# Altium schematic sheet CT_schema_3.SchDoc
size 421 x 351 mm
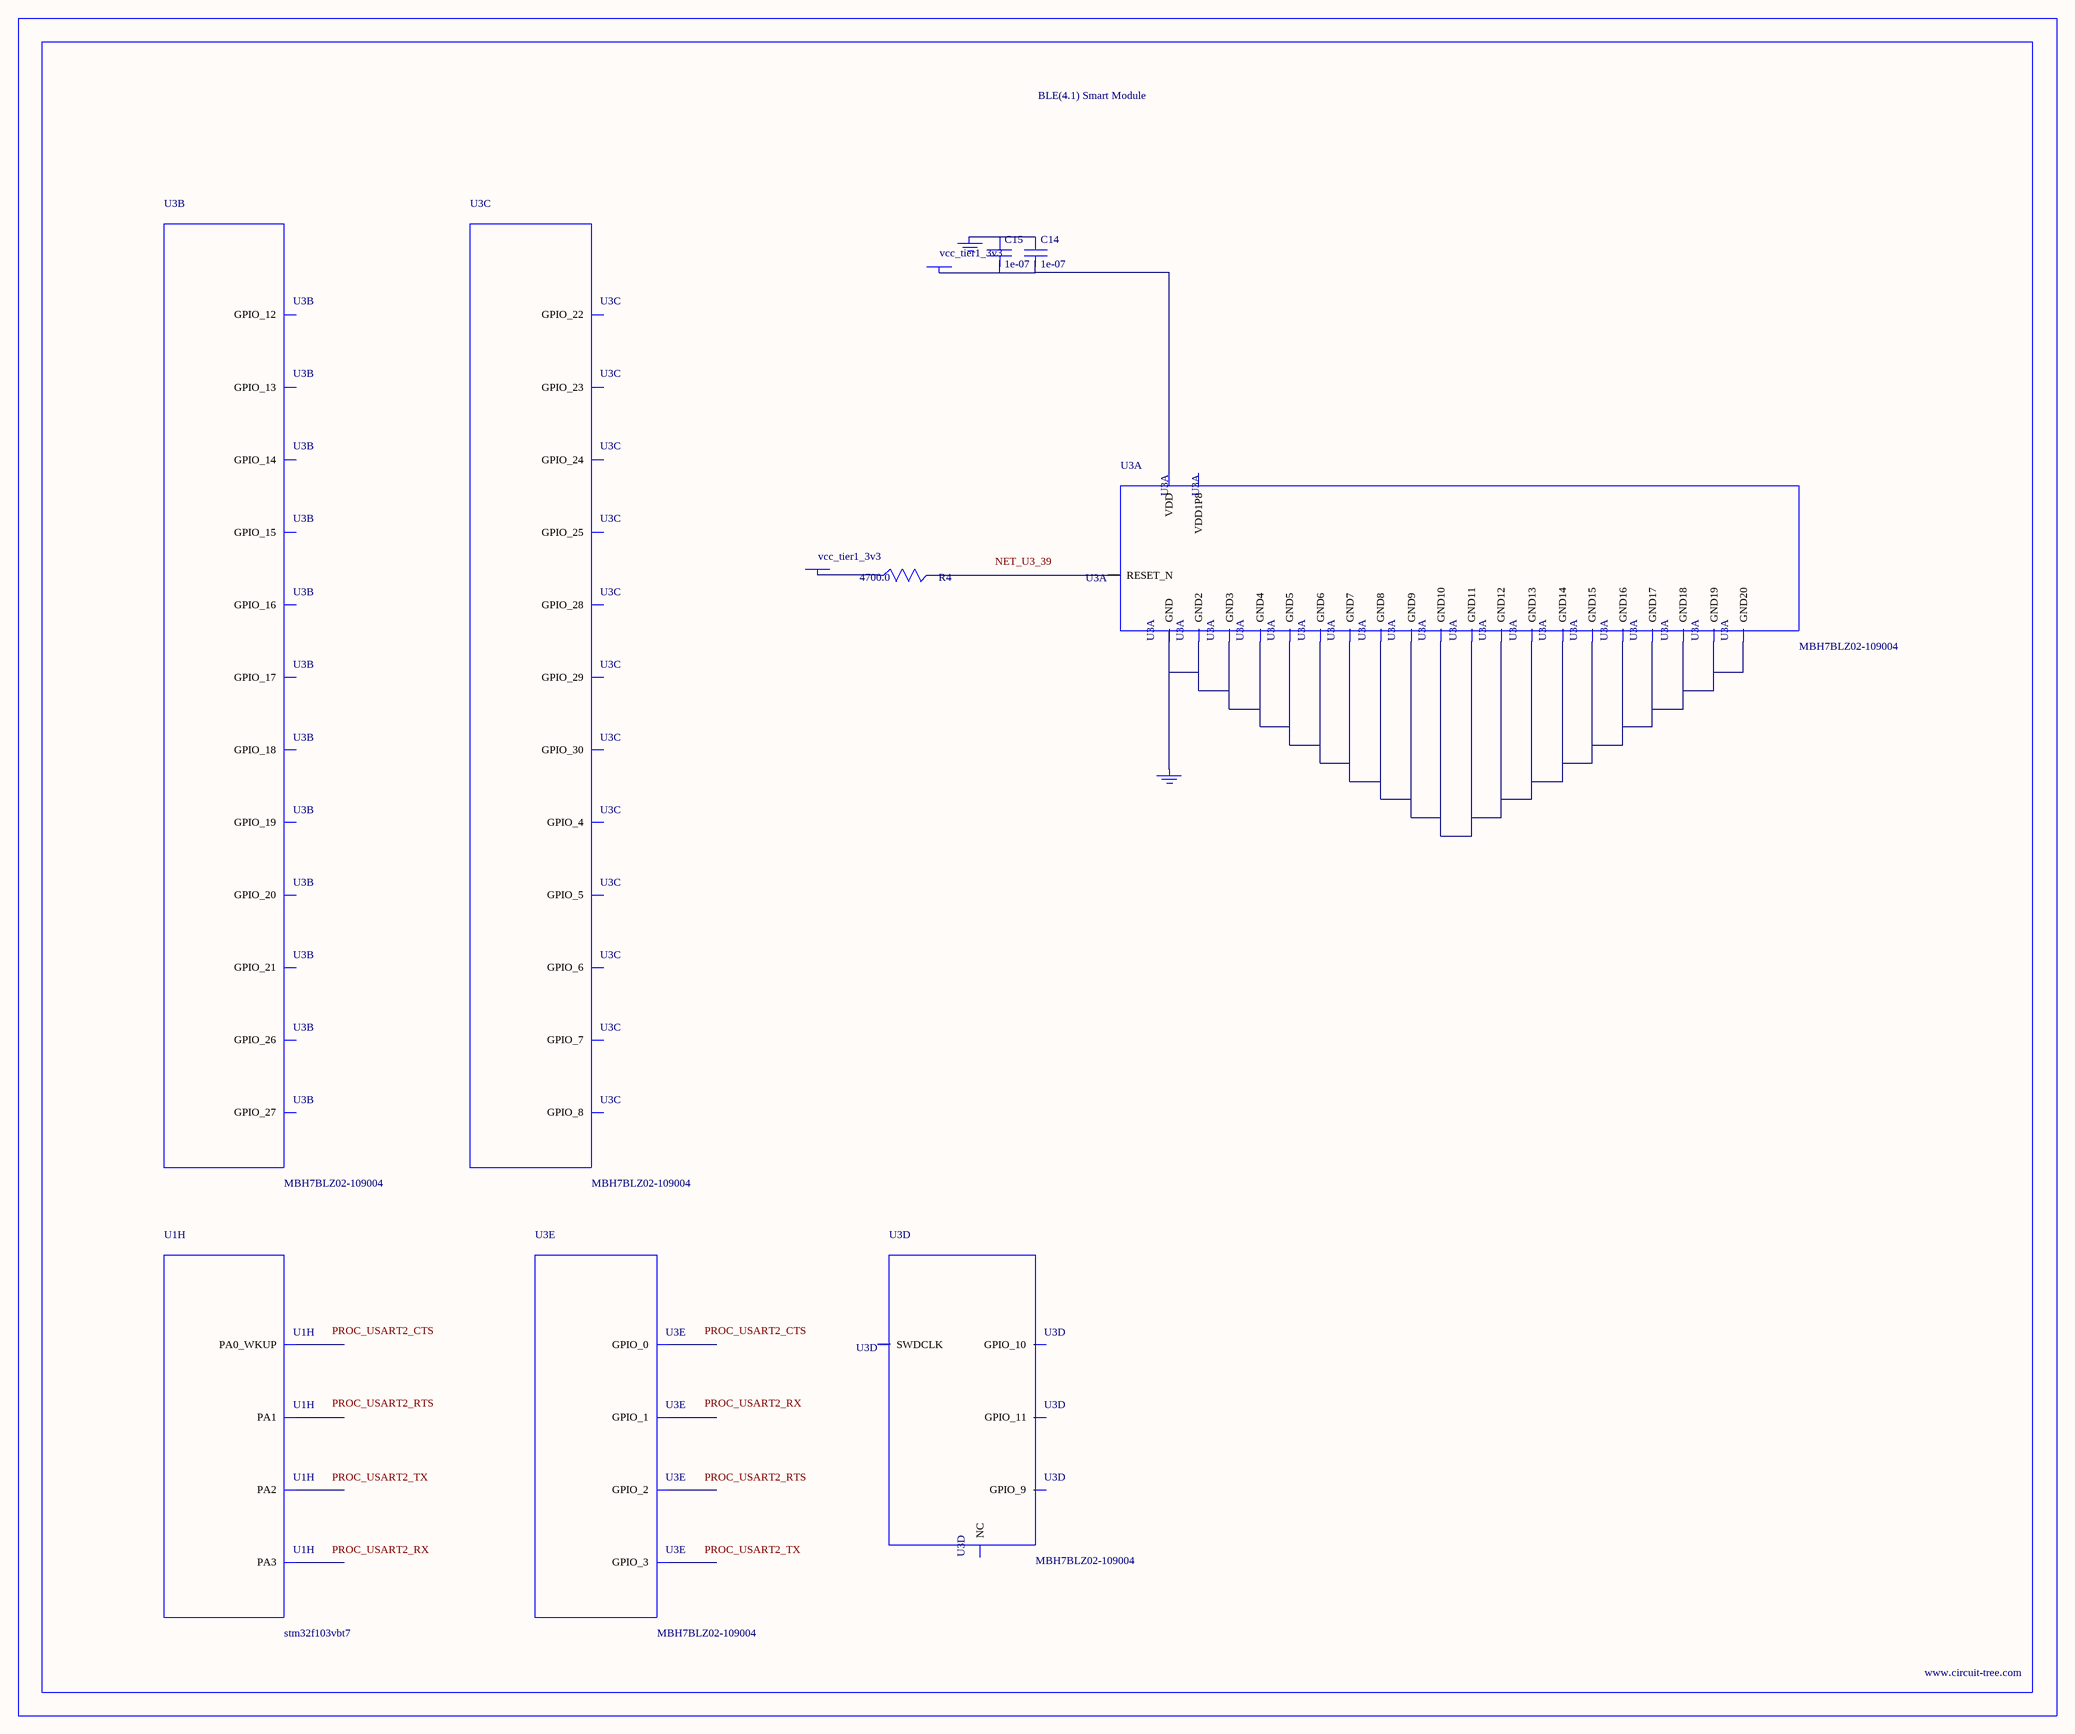
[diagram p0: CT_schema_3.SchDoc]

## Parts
BORDER2  (no value)
C14  1e-07  [C0402]
C15  1e-07  [C0402]
GND_INSTANCE_2_0  (no value)
GND_INSTANCE_2_1  (no value)
POWER_INSTANCE_2_0  vcc_tier1_3v3
POWER_INSTANCE_2_1  vcc_tier1_3v3
R4  4700.0  [R0603]
U1  stm32f103vbt7  [LQFP100]  (part H of 11)
U3  MBH7BLZ02-109004  [MBH7BLZ02-109004]  (parts A,B,C,D,E of 5)

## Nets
NetC14_1: C14.1 C15.1 GND_INSTANCE_2_0.0(GND)
NetC14_2: C14.2 C15.2 POWER_INSTANCE_2_0.0(PWR) U3.28(VDD)
NetGND_INSTANCE_2_1_0: GND_INSTANCE_2_1.0(GND) U3.1(GND) U3.3(GND2) U3.15(GND3) U3.27(GND4) U3.29(GND5) U3.41(GND6) U3.42(GND7) U3.43(GND8) U3.44(GND9) U3.45(GND10) U3.46(GND11) U3.47(GND12) U3.48(GND13) U3.49(GND14) U3.50(GND15) U3.52(GND16) U3.53(GND17) U3.54(GND18) U3.55(GND19) U3.56(GND20)
NetPOWER_INSTANCE_2_1_0: POWER_INSTANCE_2_1.0(PWR) R4.1
NetR4_2: R4.2 U3.39(RESET_N)

Not connected (* = marked no-connect by the designer): U1 23(PA0_WKUP) 24(PA1) 25(PA2) 26(PA3); U3 2(VDD1P8) 4(GPIO_17) 5(GPIO_19) 6(GPIO_18) 7(GPIO_20) 8(GPIO_16) 9(GPIO_15) 10(GPIO_14) 11(GPIO_13) 12(GPIO_12) 13(GPIO_27) 14(GPIO_26) 16(GPIO_21) 17(GPIO_22) 18(GPIO_23) 19(GPIO_24) 20(GPIO_6) 21(GPIO_5) 22(GPIO_4) 23(GPIO_3) 24(GPIO_2) 25(GPIO_1) 26(GPIO_0) 30(GPIO_25) 31(GPIO_29) 32(GPIO_28) 33(GPIO_30) 34(GPIO_7) 35(GPIO_8) 36(GPIO_9) 37(GPIO_10) 38(GPIO_11) 40(SWDCLK) 51(NC)

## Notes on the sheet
- Labels drawn without touching a wire or pin: NET_U3_39, PROC_USART2_CTS, PROC_USART2_RTS, PROC_USART2_RX, PROC_USART2_TX

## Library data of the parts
BORDER2 = BORDER_PAGE2
C14 C15 = C0402C104K3RACTU
GND_INSTANCE_2_0 GND_INSTANCE_2_1 = GND
POWER_INSTANCE_2_0 POWER_INSTANCE_2_1 = PWR
R4 = RC0603JR-074K7L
